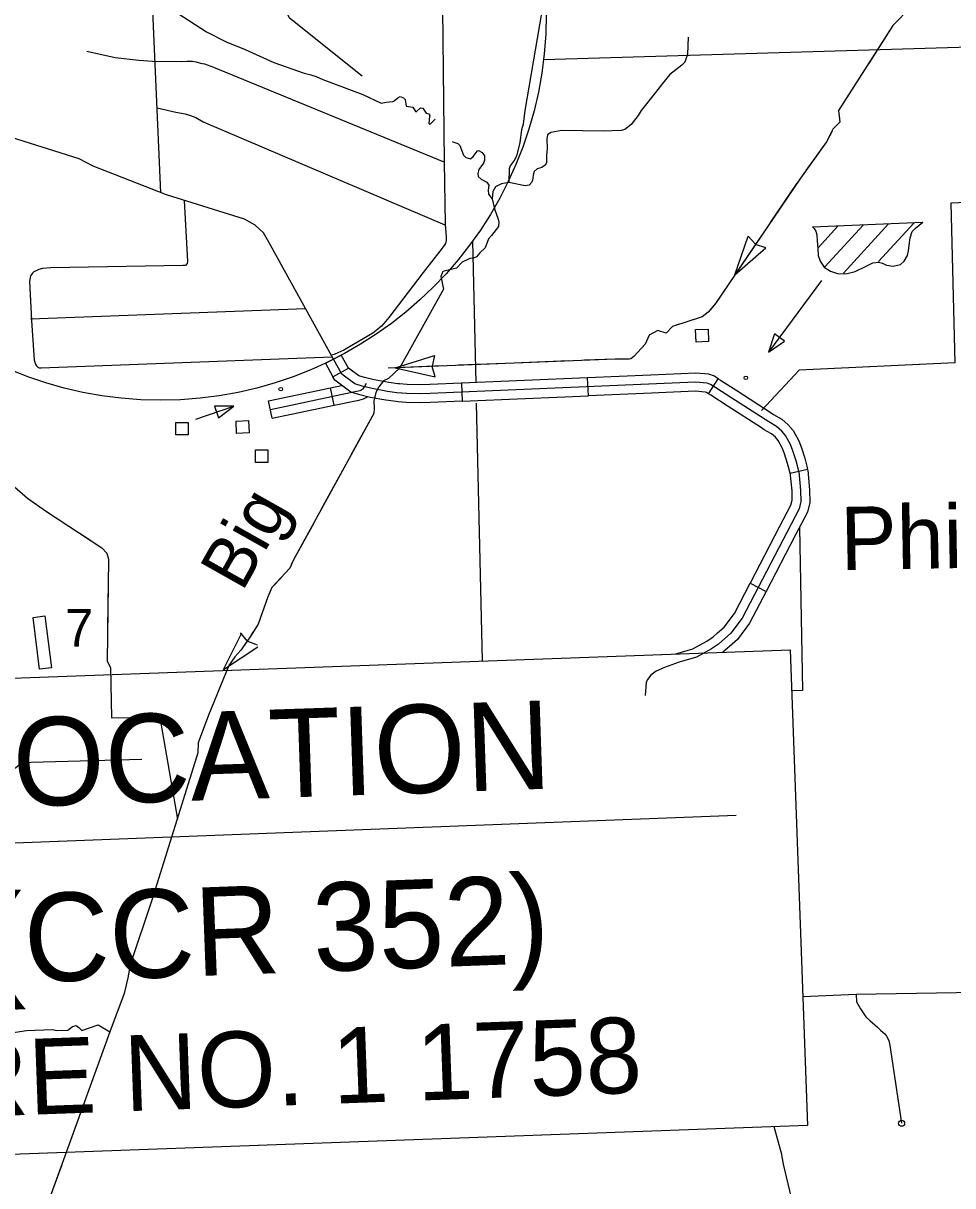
# Model space of a CAD drawing. Extents: x 1671357 to 13005564, y 567358 to 14261451.
# Drawn here: x 12758311.17 to 12758325.89, y 14259869.74 to 14259888.15 of the extents above; entities that cross this region are included whole.
import ezdxf

# ---------------------------------------------------------------- set-up
doc = ezdxf.new("R2010")
doc.units = 0
for name, color, linetype in [('24', 7, 'Continuous'), ('31', 7, 'Continuous'), ('32', 7, 'Continuous'), ('33', 7, 'Continuous'), ('34', 7, 'Continuous'), ('35', 7, 'Continuous'), ('43', 7, 'Continuous'), ('5', 7, 'Continuous'), ('56', 7, 'Continuous'), ('57', 7, 'Continuous'), ('6', 7, 'Continuous'), ('60', 7, 'Continuous'), ('63', 7, 'Continuous')]:
    doc.layers.add(name, color=color, linetype=linetype)

msp = doc.modelspace()

# ---------------------------------------------------------------- linework, layer by layer
at = {"layer": '31'}
for p, q in [((12758318.107, 14259882.453), (12758318.119, 14259882.17)), ((12758320.118, 14259882.254), (12758320.106, 14259882.538)), ((12758322.019, 14259882.286), (12758322.176, 14259882.524)), ((12758323.015, 14259881.982), (12758323.015, 14259881.982)), ((12758323.592, 14259881.086), (12758323.315, 14259881.025)), ((12758322.681, 14259879.285), (12758322.933, 14259879.154))]:
    msp.add_line(p, q, dxfattribs=at)
for points in [[(12758316.079, 14259882.832), (12758315.058, 14259884.686), (12758314.974, 14259884.835), (12758314.84, 14259884.953), (12758314.673, 14259885.048), (12758313.436, 14259885.435), (12758312.273, 14259885.888), (12758312.052, 14259886.006), (12758310.877, 14259886.374), (12758309.26, 14259886.887), (12758308.8, 14259886.971), (12758308.261, 14259887.053), (12758307.728, 14259887.237), (12758307.579, 14259887.298), (12758307.429, 14259887.401), (12758307.275, 14259887.565)], [(12758323.453, 14259881.055), (12758323.442, 14259881.104), (12758323.409, 14259881.224), (12758323.358, 14259881.383), (12758323.32, 14259881.48), (12758323.243, 14259881.624), (12758323.183, 14259881.696), (12758323.099, 14259881.769), (12758322.975, 14259881.839), (12758322.393, 14259882.216), (12758322.136, 14259882.38), (12758322.052, 14259882.435), (12758321.998, 14259882.454), (12758321.815, 14259882.468), (12758317.61, 14259882.29), (12758317.436, 14259882.285), (12758317.241, 14259882.291), (12758317.086, 14259882.302), (12758316.934, 14259882.324), (12758316.692, 14259882.367), (12758316.535, 14259882.406), (12758316.417, 14259882.441), (12758316.21, 14259882.595), (12758316.08, 14259882.831)], [(12758317.125, 14259882.442), (12758317.101, 14259882.444), (12758316.957, 14259882.464), (12758316.722, 14259882.506), (12758316.572, 14259882.543), (12758316.482, 14259882.57), (12758316.319, 14259882.69), (12758316.32, 14259882.689)], [(12758317.103, 14259882.159), (12758317.071, 14259882.161), (12758316.912, 14259882.183), (12758316.662, 14259882.228), (12758316.497, 14259882.269), (12758316.353, 14259882.311), (12758316.1, 14259882.499), (12758316.071, 14259882.552)], [(12758318.107, 14259882.453), (12758317.604, 14259882.432), (12758317.436, 14259882.427), (12758317.248, 14259882.433), (12758317.125, 14259882.442)], [(12758319.106, 14259882.496), (12758318.107, 14259882.453)], [(12758320.106, 14259882.538), (12758319.106, 14259882.496)], [(12758321.105, 14259882.58), (12758320.106, 14259882.538)], [(12758322.176, 14259882.524), (12758322.115, 14259882.563), (12758322.027, 14259882.594), (12758321.818, 14259882.61), (12758321.105, 14259882.58)], [(12758322.176, 14259882.524), (12758322.213, 14259882.499), (12758322.47, 14259882.335), (12758323.015, 14259881.982)], [(12758321.117, 14259882.296), (12758320.118, 14259882.254)], [(12758322.019, 14259882.286), (12758321.989, 14259882.306), (12758321.969, 14259882.313), (12758321.813, 14259882.325), (12758321.117, 14259882.296)], [(12758322.861, 14259881.744), (12758322.316, 14259882.096), (12758322.058, 14259882.261), (12758322.019, 14259882.286)], [(12758318.119, 14259882.17), (12758317.615, 14259882.148), (12758317.436, 14259882.143), (12758317.233, 14259882.149), (12758317.103, 14259882.159)], [(12758318.119, 14259882.17), (12758319.118, 14259882.212)], [(12758319.118, 14259882.212), (12758320.118, 14259882.254)], [(12758323.015, 14259881.982), (12758323.049, 14259881.96), (12758323.181, 14259881.886), (12758323.285, 14259881.795), (12758323.361, 14259881.704), (12758323.45, 14259881.54), (12758323.492, 14259881.43), (12758323.545, 14259881.265), (12758323.58, 14259881.139), (12758323.592, 14259881.086)], [(12758323.315, 14259881.025), (12758323.305, 14259881.069), (12758323.272, 14259881.183), (12758323.224, 14259881.335), (12758323.191, 14259881.421), (12758323.125, 14259881.544), (12758323.081, 14259881.596), (12758323.017, 14259881.653), (12758322.902, 14259881.717), (12758322.861, 14259881.744)], [(12758323.312, 14259881.045), (12758323.339, 14259880.747), (12758323.342, 14259880.594), (12758323.322, 14259880.514), (12758323.143, 14259880.172)], [(12758323.594, 14259881.078), (12758323.623, 14259880.763), (12758323.627, 14259880.562), (12758323.589, 14259880.412), (12758323.395, 14259880.04)], [(12758323.453, 14259881.055), (12758323.481, 14259880.755), (12758323.485, 14259880.578), (12758323.455, 14259880.463)], [(12758323.455, 14259880.463), (12758322.552, 14259878.731), (12758322.374, 14259878.493), (12758322.18, 14259878.322), (12758322.07, 14259878.247), (12758321.829, 14259878.117), (12758321.557, 14259878.034), (12758321.322, 14259877.952), (12758321.19, 14259877.893), (12758321.107, 14259877.831), (12758321.053, 14259877.762), (12758321.036, 14259877.714), (12758321.018, 14259877.506)], [(12758323.143, 14259880.172), (12758322.681, 14259879.285)], [(12758323.395, 14259880.04), (12758322.933, 14259879.154)], [(12758322.166, 14259878.499), (12758322.269, 14259878.59), (12758322.431, 14259878.807), (12758322.681, 14259879.285)], [(12758322.933, 14259879.154), (12758322.672, 14259878.655), (12758322.479, 14259878.397), (12758322.354, 14259878.286)], [(12758321.506, 14259878.167), (12758321.774, 14259878.249), (12758321.996, 14259878.369), (12758322.093, 14259878.435), (12758322.166, 14259878.499)], [(12758322.354, 14259878.286), (12758322.25, 14259878.194)]]:
    msp.add_lwpolyline(points, dxfattribs=at)
msp.add_lwpolyline([(12758316.071, 14259882.552), (12758316.32, 14259882.689), (12758316.204, 14259882.899), (12758316.079, 14259882.832), (12758315.955, 14259882.771), (12758316.071, 14259882.552)], close=True, dxfattribs=at)
at = {"layer": '32'}
for p, q in [((12758316.089, 14259882.104), (12758316.031, 14259882.382)), ((12758315.111, 14259881.897), (12758315.052, 14259882.175))]:
    msp.add_line(p, q, dxfattribs=at)
for points in [[(12758313.347, 14259885.47), (12758313.21, 14259888.595), (12758313.17, 14259890.262), (12758313.153, 14259892.354), (12758313.098, 14259894.4)], [(12758317.794, 14259889.347), (12758317.836, 14259885.96), (12758317.852, 14259884.971), (12758317.867, 14259884.77), (12758317.867, 14259884.736), (12758317.864, 14259884.711), (12758317.854, 14259884.667), (12758317.831, 14259884.632), (12758317.764, 14259884.542), (12758317.501, 14259884.208), (12758316.956, 14259883.492), (12758316.878, 14259883.396), (12758316.842, 14259883.356), (12758316.822, 14259883.34), (12758316.785, 14259883.307), (12758316.706, 14259883.243), (12758316.243, 14259882.974), (12758316.148, 14259882.934), (12758316.09, 14259882.909), (12758316.044, 14259882.895)], [(12758316.532, 14259887.313), (12758315.43, 14259888.197), (12758315.385, 14259888.235), (12758315.36, 14259888.28), (12758315.354, 14259888.31), (12758315.354, 14259888.348), (12758315.362, 14259888.521)], [(12758312.175, 14259887.711), (12758312.621, 14259887.611), (12758312.996, 14259887.568), (12758313.213, 14259887.552), (12758313.672, 14259887.545), (12758313.763, 14259887.551), (12758313.848, 14259887.554), (12758313.903, 14259887.543), (12758313.974, 14259887.523), (12758314.035, 14259887.512), (12758314.177, 14259887.459), (12758317.828, 14259885.959)], [(12758313.289, 14259886.811), (12758313.584, 14259886.744), (12758313.733, 14259886.716), (12758313.813, 14259886.692), (12758313.898, 14259886.658), (12758314.018, 14259886.594), (12758317.843, 14259884.963)], [(12758313.715, 14259885.348), (12758313.765, 14259884.38), (12758313.761, 14259884.346), (12758313.735, 14259884.318), (12758313.696, 14259884.315), (12758311.601, 14259884.279), (12758311.47, 14259884.272), (12758311.41, 14259884.253), (12758311.371, 14259884.232), (12758311.334, 14259884.216), (12758311.314, 14259884.196), (12758311.281, 14259884.153), (12758311.264, 14259884.061), (12758311.298, 14259883.447), (12758311.339, 14259882.82), (12758311.359, 14259882.756), (12758311.377, 14259882.73), (12758311.397, 14259882.706), (12758311.418, 14259882.699), (12758311.45, 14259882.698), (12758316.058, 14259882.87)], [(12758311.28, 14259883.473), (12758315.636, 14259883.636)], [(12758315.082, 14259882.036), (12758316.446, 14259882.325), (12758316.505, 14259882.34), (12758316.551, 14259882.363), (12758316.574, 14259882.396), (12758316.601, 14259882.454)], [(12758315.052, 14259882.175), (12758316.031, 14259882.382)], [(12758316.031, 14259882.382), (12758316.208, 14259882.419)], [(12758315.111, 14259881.897), (12758316.089, 14259882.104)], [(12758316.089, 14259882.104), (12758316.48, 14259882.187), (12758316.555, 14259882.207), (12758316.619, 14259882.238)], [(12758313.044, 14259876.495), (12758311.283, 14259876.449), (12758311.243, 14259876.441), (12758311.166, 14259876.427), (12758311.095, 14259876.399), (12758310.946, 14259876.29), (12758310.882, 14259876.242), (12758310.707, 14259876.214), (12758309.74, 14259876.124), (12758309.19, 14259876.116), (12758308.481, 14259876.111)]]:
    msp.add_lwpolyline(points, dxfattribs=at)
at = {"layer": '33'}
for points in [[(12758328.715, 14259872.82), (12758327.932, 14259872.817), (12758327.221, 14259872.822), (12758324.36, 14259872.775), (12758323.518, 14259872.736)], [(12758323.058, 14259870.681), (12758323.17, 14259870.268), (12758323.204, 14259870.085), (12758323.249, 14259869.886), (12758323.302, 14259869.666), (12758323.334, 14259869.53), (12758323.369, 14259869.421), (12758323.405, 14259869.33), (12758323.476, 14259869.228), (12758323.565, 14259869.141), (12758323.624, 14259869.092), (12758323.674, 14259869.037), (12758323.723, 14259868.957), (12758323.745, 14259868.873), (12758323.768, 14259868.75), (12758323.766, 14259867.691), (12758325.981, 14259867.763)]]:
    msp.add_lwpolyline(points, dxfattribs=at)
at = {"layer": '34'}
msp.add_lwpolyline([(12758324.36, 14259872.775), (12758324.367, 14259872.656), (12758324.431, 14259872.548), (12758324.516, 14259872.421), (12758324.575, 14259872.36), (12758324.697, 14259872.255), (12758324.752, 14259872.205), (12758324.812, 14259872.15), (12758324.842, 14259872.112), (12758324.877, 14259872.045), (12758324.895, 14259871.964), (12758325.081, 14259870.734)], dxfattribs=at)
msp.add_circle((12758325.081, 14259870.734), 0.0474, dxfattribs=at)
at = {"layer": '35'}
for points in [[(12758319.461, 14259888.615), (12758319.409, 14259888.499), (12758319.11, 14259886.771), (12758319.085, 14259886.555), (12758319.06, 14259886.465), (12758319.032, 14259886.266), (12758318.981, 14259886.047), (12758318.942, 14259885.979), (12758318.879, 14259885.895), (12758318.862, 14259885.845), (12758318.856, 14259885.632)], [(12758313.508, 14259888.375), (12758313.529, 14259888.364), (12758314.067, 14259888.019), (12758314.381, 14259887.858), (12758314.68, 14259887.737), (12758315.136, 14259887.53), (12758315.617, 14259887.36), (12758315.722, 14259887.336)], [(12758321.698, 14259887.931), (12758321.689, 14259887.661), (12758321.647, 14259887.536), (12758321.6, 14259887.488), (12758321.41, 14259887.342), (12758321.295, 14259887.198)], [(12758315.722, 14259887.336), (12758315.805, 14259887.309), (12758315.909, 14259887.26), (12758316.545, 14259887.025), (12758316.833, 14259886.89), (12758316.914, 14259886.903), (12758317.02, 14259886.913), (12758317.042, 14259886.924), (12758317.097, 14259886.97), (12758317.138, 14259886.991), (12758317.188, 14259886.972), (12758317.216, 14259886.948), (12758317.232, 14259886.841), (12758317.339, 14259886.822), (12758317.377, 14259886.756), (12758317.389, 14259886.748), (12758317.458, 14259886.814), (12758317.493, 14259886.806), (12758317.549, 14259886.73), (12758317.589, 14259886.719), (12758317.604, 14259886.693), (12758317.599, 14259886.679), (12758317.592, 14259886.565), (12758317.608, 14259886.55), (12758317.69, 14259886.636)], [(12758321.295, 14259887.198), (12758321.183, 14259887.057), (12758320.953, 14259886.77), (12758320.909, 14259886.692), (12758320.797, 14259886.552), (12758320.694, 14259886.468), (12758320.636, 14259886.455), (12758320.35, 14259886.443), (12758319.696, 14259886.455), (12758319.523, 14259886.423), (12758319.469, 14259886.385), (12758319.459, 14259886.318), (12758319.467, 14259886.172), (12758319.456, 14259886.058), (12758319.454, 14259885.945), (12758319.433, 14259885.905), (12758319.381, 14259885.868), (12758319.306, 14259885.846), (12758319.26, 14259885.803), (12758319.242, 14259885.749), (12758319.232, 14259885.665), (12758319.22, 14259885.636), (12758319.18, 14259885.588), (12758319.118, 14259885.58), (12758318.856, 14259885.632), (12758318.74, 14259885.612), (12758318.649, 14259885.564), (12758318.606, 14259885.488), (12758318.592, 14259885.374), (12758318.629, 14259885.212), (12758318.689, 14259885.049), (12758318.697, 14259885.002)], [(12758317.966, 14259886.278), (12758317.972, 14259886.277), (12758318.049, 14259886.248), (12758318.084, 14259886.219), (12758318.138, 14259886.064), (12758318.178, 14259886.027), (12758318.251, 14259886.007), (12758318.293, 14259886.043), (12758318.359, 14259886.133), (12758318.376, 14259886.138), (12758318.436, 14259886.106), (12758318.471, 14259886.055), (12758318.472, 14259885.986), (12758318.457, 14259885.938), (12758318.385, 14259885.836), (12758318.367, 14259885.773), (12758318.374, 14259885.728), (12758318.42, 14259885.682), (12758318.509, 14259885.638), (12758318.541, 14259885.59), (12758318.531, 14259885.51), (12758318.538, 14259885.449), (12758318.592, 14259885.374)], [(12758318.697, 14259885.002), (12758318.692, 14259884.937), (12758318.581, 14259884.794), (12758318.537, 14259884.737), (12758318.483, 14259884.596), (12758318.401, 14259884.515), (12758318.346, 14259884.454), (12758318.3, 14259884.433), (12758318.241, 14259884.427), (12758318.117, 14259884.37), (12758318.03, 14259884.273), (12758317.812, 14259884.221), (12758317.779, 14259884.145), (12758317.822, 14259883.944), (12758317.126, 14259882.691), (12758316.954, 14259882.526)]]:
    msp.add_lwpolyline(points, dxfattribs=at)
at = {"layer": '43'}
for p, q in [((12758322.44, 14259884.169), (12758322.652, 14259884.784)), ((12758322.652, 14259884.784), (12758322.766, 14259884.653)), ((12758322.44, 14259884.169), (12758322.931, 14259884.595)), ((12758322.931, 14259884.595), (12758322.768, 14259884.652)), ((12758317.059, 14259882.697), (12758317.679, 14259882.89)), ((12758317.679, 14259882.89), (12758317.641, 14259882.721)), ((12758317.059, 14259882.697), (12758317.693, 14259882.554)), ((12758317.693, 14259882.554), (12758317.641, 14259882.719)), ((12758314.34, 14259877.92), (12758314.63, 14259878.502)), ((12758314.6, 14259878.502), (12758314.711, 14259878.369)), ((12758314.34, 14259877.92), (12758314.882, 14259878.279)), ((12758314.875, 14259878.307), (12758314.713, 14259878.367))]:
    msp.add_line(p, q, dxfattribs=at)
for points in [[(12758326.034, 14259891.24), (12758325.315, 14259888.529), (12758325.301, 14259888.494), (12758325.234, 14259888.411), (12758324.943, 14259888.115), (12758324.082, 14259886.773), (12758324.102, 14259886.584), (12758323.993, 14259886.474), (12758323.893, 14259886.275), (12758323.477, 14259885.702), (12758322.132, 14259883.715), (12758322.014, 14259883.576), (12758321.92, 14259883.503), (12758321.45, 14259883.351), (12758321.35, 14259883.247), (12758321.217, 14259883.286), (12758321.079, 14259883.215), (12758321.019, 14259883.069), (12758320.839, 14259882.877), (12758320.79, 14259882.84), (12758320.766, 14259882.832), (12758320.545, 14259882.835), (12758316.948, 14259882.693)], [(12758324.964, 14259888.136), (12758324.943, 14259888.115), (12758324.554, 14259887.509)], [(12758324.419, 14259887.298), (12758324.082, 14259886.773), (12758324.095, 14259886.647)], [(12758323.979, 14259886.446), (12758323.893, 14259886.275), (12758323.565, 14259885.823)], [(12758323.421, 14259885.619), (12758323, 14259884.998)], [(12758322.86, 14259884.79), (12758322.44, 14259884.169)], [(12758322.3, 14259883.962), (12758322.132, 14259883.715), (12758322.083, 14259883.657)], [(12758322.083, 14259883.657), (12758322.014, 14259883.576), (12758321.92, 14259883.503), (12758321.777, 14259883.457)], [(12758321.539, 14259883.38), (12758321.45, 14259883.351), (12758321.35, 14259883.247), (12758321.217, 14259883.286), (12758321.079, 14259883.215), (12758321.019, 14259883.069), (12758320.978, 14259883.025)], [(12758320.802, 14259882.849), (12758320.79, 14259882.84), (12758320.766, 14259882.832), (12758320.545, 14259882.835), (12758320.057, 14259882.816)], [(12758317.808, 14259882.727), (12758317.059, 14259882.697)], [(12758318.807, 14259882.766), (12758318.058, 14259882.736)], [(12758319.807, 14259882.806), (12758319.057, 14259882.776)], [(12758316.954, 14259882.526), (12758316.874, 14259882.489), (12758316.8, 14259882.398), (12758316.751, 14259882.305), (12758316.719, 14259882.169), (12758316.726, 14259882.057), (12758316.72, 14259881.975), (12758315.446, 14259879.654), (12758315.387, 14259879.522), (12758315.106, 14259879.216), (12758315.039, 14259879.069), (12758314.886, 14259878.639), (12758314.747, 14259878.419), (12758314.611, 14259878.227), (12758314.515, 14259878.118), (12758314.423, 14259877.981), (12758314.101, 14259877.198)], [(12758316.954, 14259882.526), (12758316.874, 14259882.489), (12758316.861, 14259882.473)], [(12758316.721, 14259881.995), (12758316.72, 14259881.975), (12758316.368, 14259881.335)], [(12758309.994, 14259881.708), (12758311.232, 14259880.635), (12758311.536, 14259880.424), (12758312.41, 14259879.846), (12758312.488, 14259879.76), (12758312.516, 14259879.665), (12758312.495, 14259878.051), (12758312.547, 14259877.951), (12758312.565, 14259877.154), (12758313.329, 14259877.157), (12758313.609, 14259875.55)], [(12758316.248, 14259881.116), (12758315.887, 14259880.458)], [(12758311.222, 14259880.643), (12758311.232, 14259880.635), (12758311.536, 14259880.424), (12758311.842, 14259880.222)], [(12758312.051, 14259880.084), (12758312.41, 14259879.846), (12758312.488, 14259879.76), (12758312.516, 14259879.665), (12758312.515, 14259879.561)], [(12758315.767, 14259880.239), (12758315.446, 14259879.654), (12758315.412, 14259879.578)], [(12758315.26, 14259879.383), (12758315.106, 14259879.216), (12758315.039, 14259879.069), (12758314.918, 14259878.728)], [(12758312.512, 14259879.311), (12758312.502, 14259878.561)], [(12758314.803, 14259878.508), (12758314.747, 14259878.419), (12758314.611, 14259878.227), (12758314.515, 14259878.118), (12758314.423, 14259877.981), (12758314.385, 14259877.889)], [(12758314.101, 14259877.198), (12758313.934, 14259876.759), (12758313.933, 14259876.599), (12758313.207, 14259874.285)], [(12758313.207, 14259874.285), (12758312.861, 14259873.244), (12758312.824, 14259873.039), (12758312.765, 14259872.789), (12758312.537, 14259872.18), (12758308.447, 14259860.899), (12758308.454, 14259860.785), (12758307.78, 14259859.026)], [(12758309.603, 14259872.107), (12758309.788, 14259872.034), (12758309.922, 14259872.104), (12758310.168, 14259872.147), (12758310.385, 14259872.115), (12758310.528, 14259872.108), (12758310.749, 14259872.155), (12758310.907, 14259872.157), (12758311.217, 14259872.201), (12758311.628, 14259872.217), (12758311.695, 14259872.202), (12758311.873, 14259872.208), (12758311.948, 14259872.265), (12758312.004, 14259872.28), (12758312.047, 14259872.252), (12758312.094, 14259872.205), (12758312.35, 14259872.292), (12758312.537, 14259872.18)], [(12758311.775, 14259870.077), (12758311.519, 14259869.372)]]:
    msp.add_lwpolyline(points, dxfattribs=at)
at = {"layer": '5'}
for points in [[(12758319.409, 14259887.578), (12758327.941, 14259887.832)], [(12758318.338, 14259882.457), (12758318.286, 14259884.704)], [(12758318.442, 14259878.055), (12758318.346, 14259882.137)]]:
    msp.add_lwpolyline(points, dxfattribs=at)
at = {"layer": '56'}
for points in [[(12758323.812, 14259884.079), (12758322.973, 14259882.945)], [(12758313.897, 14259881.886), (12758314.501, 14259882.089)]]:
    msp.add_lwpolyline(points, dxfattribs=at)
for points in [[(12758321.825, 14259883.104), (12758321.817, 14259883.301), (12758322.015, 14259883.309), (12758322.023, 14259883.112)], [(12758323.223, 14259883.121), (12758323.068, 14259883.236), (12758322.973, 14259882.945)], [(12758314.196, 14259882.088), (12758314.257, 14259881.905), (12758314.501, 14259882.089)], [(12758313.58, 14259881.636), (12758313.58, 14259881.833), (12758313.778, 14259881.833), (12758313.778, 14259881.636)], [(12758314.545, 14259881.657), (12758314.536, 14259881.854), (12758314.734, 14259881.862), (12758314.742, 14259881.665)], [(12758314.844, 14259881.199), (12758314.844, 14259881.396), (12758315.042, 14259881.396), (12758315.042, 14259881.199)], [(12758311.321, 14259878.745), (12758311.509, 14259878.768), (12758311.611, 14259877.946), (12758311.423, 14259877.923)]]:
    msp.add_lwpolyline(points, close=True, dxfattribs=at)
for centre in [(12758322.613, 14259882.538), (12758315.245, 14259882.359)]:
    msp.add_circle(centre, 0.0284, dxfattribs=at)
at = {"layer": '57'}
for p, q in [((12758323.67, 14259884.931), (12758325.419, 14259885.004)), ((12758323.756, 14259884.598), (12758324.071, 14259884.941)), ((12758323.866, 14259884.298), (12758324.471, 14259884.955)), ((12758324.159, 14259884.197), (12758324.875, 14259884.975)), ((12758324.713, 14259884.379), (12758325.273, 14259884.988))]:
    msp.add_line(p, q, dxfattribs=at)
msp.add_lwpolyline([(12758323.67, 14259884.931), (12758323.696, 14259884.904), (12758323.721, 14259884.863), (12758323.739, 14259884.801), (12758323.743, 14259884.707), (12758323.751, 14259884.585), (12758323.756, 14259884.475), (12758323.791, 14259884.385), (12758323.855, 14259884.293), (12758323.952, 14259884.229), (12758324.063, 14259884.192), (12758324.197, 14259884.185), (12758324.347, 14259884.22), (12758324.519, 14259884.305), (12758324.624, 14259884.357), (12758324.715, 14259884.368), (12758324.779, 14259884.353), (12758324.843, 14259884.324), (12758324.946, 14259884.305), (12758325.063, 14259884.331), (12758325.123, 14259884.385), (12758325.172, 14259884.474), (12758325.192, 14259884.551), (12758325.201, 14259884.64), (12758325.218, 14259884.753), (12758325.25, 14259884.857), (12758325.298, 14259884.906), (12758325.358, 14259884.958), (12758325.419, 14259885.004)], dxfattribs=at)
at = {"layer": '6'}
for points in [[(12758333.495, 14259885.594), (12758328.348, 14259885.407), (12758325.859, 14259885.305), (12758325.926, 14259882.773), (12758323.46, 14259882.659), (12758322.861, 14259882.019)], [(12758323.461, 14259880.168), (12758323.512, 14259877.589), (12758323.341, 14259877.582)]]:
    msp.add_lwpolyline(points, dxfattribs=at)
at = {"layer": '60'}
msp.add_line((12758299.766, 14259874.745), (12758322.461, 14259875.613), dxfattribs=at)
msp.add_lwpolyline([(12758299.67, 14259877.369), (12758323.317, 14259878.233), (12758323.592, 14259870.7), (12758299.945, 14259869.836)], close=True, dxfattribs=at)
at = {"layer": '63'}
msp.add_circle((12758313.341, 14259888.294), 6.11, dxfattribs=at)

# ---------------------------------------------------------------- texts
at = {"layer": '24'}
msp.add_text('Philadelphia', height=1.00013, rotation=1, dxfattribs=at).set_placement((12758324.118, 14259879.493))
at = {"layer": '43'}
msp.add_text('Big', height=0.8001, rotation=60.6136, dxfattribs=at).set_placement((12758314.634, 14259879.136))
at = {"layer": '56'}
msp.add_text('7', height=0.6, dxfattribs=at).set_placement((12758311.829, 14259878.28))
at = {"layer": '60'}
for s, height, rotation, p in [('PROJECT LOCATION', 1.4, 1.939, (12758300.729, 14259875.397)), ('CO. RD. 27 (CCR 352)', 1.4, 2.1539, (12758300.39, 14259872.555)), ('STRUCTURE NO. 1 1758', 1.2, 2.0889, (12758302.447, 14259870.546))]:
    msp.add_text(s, height=height, rotation=rotation, dxfattribs=at).set_placement(p)

doc.saveas('drawing.dxf')
